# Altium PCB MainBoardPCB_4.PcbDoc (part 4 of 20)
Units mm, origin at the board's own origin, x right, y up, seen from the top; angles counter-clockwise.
Board outline 333.63 x 349.38 mm, 16 copper layers (L1, L2 (GND), L3 (Sign), L4 (GND), L5 (Sign), L6 (PWR/GND), L7(PWR/GND), L8 (Plane_GND), L9 (PWR/GND), L10 (PWR/GND), L11 (PWR/GND), L12 (Sign), L13 (GND), L14 (Sign), L15 (GND), L16), stack 2.502 mm thick; 2205 components, 1648 nets, 8314 pads, 3172 vias.
Unrouted connection lines stored in the file: 5141.
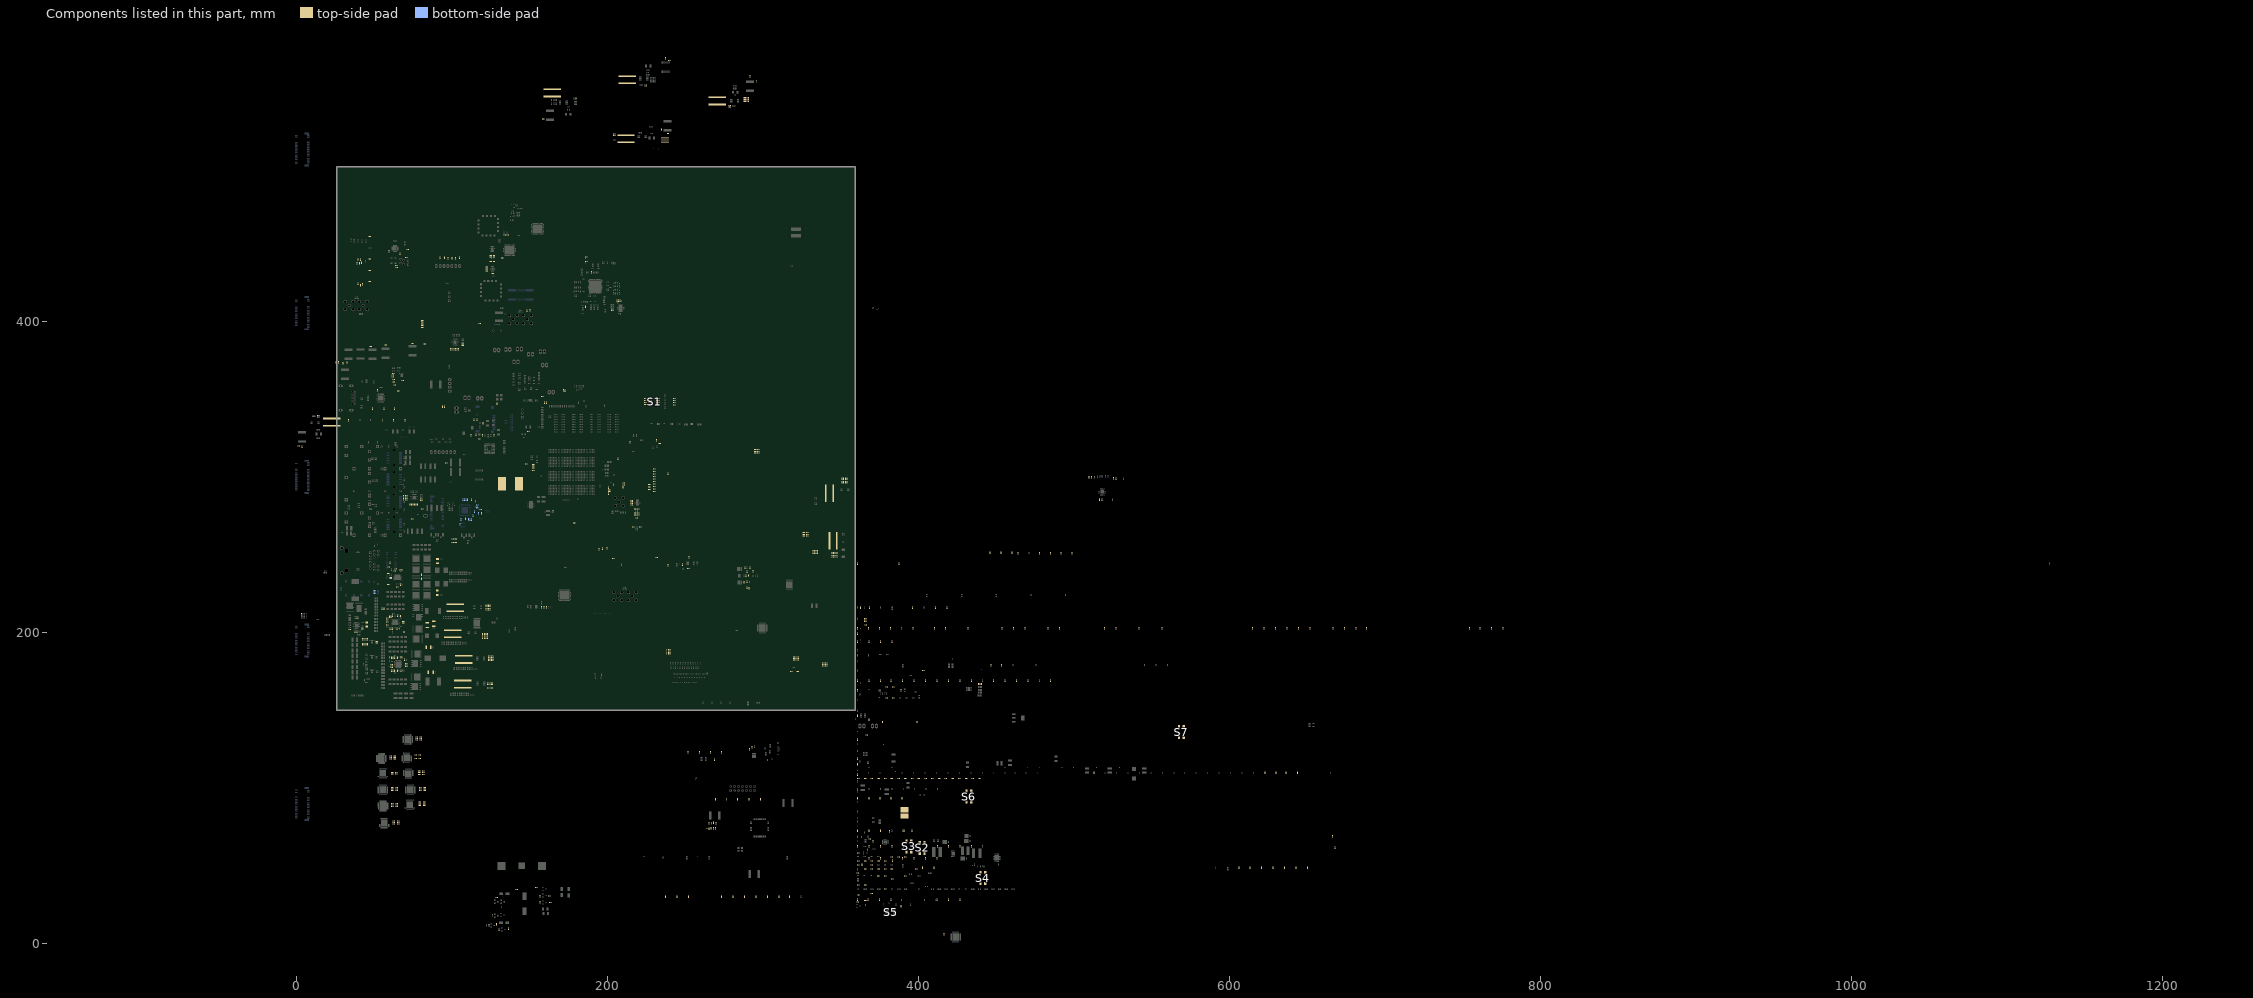
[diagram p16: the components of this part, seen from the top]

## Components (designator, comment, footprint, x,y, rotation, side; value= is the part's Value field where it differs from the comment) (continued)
R199 "0mR" "RES 0402/1005 RF" 3.202,211.734 r90 top
R200 "1.02kR" "RES 0402/1005 RF" 14.092,339.522 r0 top
R201 "0mR" "RES 0402/1005 RF" 288.214,541.35 r180 top
R202 "0mR" "RES 0402/1005 RF" 288.214,542.239 r180 top
R203 "0mR" "RES 0402/1005 RF" 288.214,543.128 r180 top
R204 "0mR" "RES 0402/1005 RF" 288.214,544.017 r180 top
R205 "0mR" "RES 0402/1005 RF" 290.373,541.35 r0 top
R206 "0mR" "RES 0402/1005 RF" 290.373,542.239 r0 top
R207 "0mR" "RES 0402/1005 RF" 290.373,543.128 r0 top
R208 "0mR" "RES 0402/1005 RF" 290.373,544.017 r0 top
R209 "1.02kR" "RES 0402/1005 RF" 278.586,537.724 r180 top
R210 "0mR" "RES 0402/1005 RF" 235.255,515.493 r270 top
R211 "0mR" "RES 0402/1005 RF" 236.525,515.493 r270 top
R212 "12.5k" "RES 0402/1005 RF" 179.728,543.303 r90 top
R213 "0mR" "RES 0402/1005 RF" 237.795,515.493 r270 top
R214 "10kR" "RES 0402/1005 RF" 224.745,551.227 r0 top
R215 "0mR" "RES 0402/1005 RF" 239.065,515.493 r270 top
R216 "31.2kR" "RES 0402/1005 RF" 14.092,338.379 r0 top
R217 "0mR" "RES 0402/1005 RF" 235.255,517.71 r90 top
R218 "10kR" "RES 0402/1005 RF" 278.793,538.867 r180 top
R219 "0mR" "RES 0402/1005 RF" 236.525,517.71 r90 top
R220 "4.99kR" "RES 0402/1005 RF" 205.029,520.065 r90 top
R221 "0mR" "RES 0402/1005 RF" 237.795,517.71 r90 top
R222 "0mR" "RES 0402/1005 RF" 239.065,517.71 r90 top
R223_I2C_Bridge "1kR" "RES 0402/1005 RF" 106.896,385.48 r0 top (schematic designator R223)
R223_I2C_Bridge_2 "1kR" "RES 0402/1005 RF" 509.782,299.86 r90 top (schematic designator R223)
R223_I2C_Bridge_3 "1kR" "RES 0402/1005 RF" 80.422,285.86 r0 top (schematic designator R223)
R224_I2C_Bridge "1kR" "RES 0402/1005 RF" 106.896,384.424 r0 top (schematic designator R224)
R224_I2C_Bridge_2 "1kR" "RES 0402/1005 RF" 525.403,299.047 r90 top (schematic designator R224)
R224_I2C_Bridge_3 "1kR" "RES 0402/1005 RF" 80.422,284.886 r0 top (schematic designator R224)
R225_I2C_Bridge "1kR" "RES 0402/1005 RF" 104.356,382.099 r270 top (schematic designator R225)
R225_I2C_Bridge_2 "1kR" "RES 0402/1005 RF" 516.572,285.382 r90 top (schematic designator R225)
R225_I2C_Bridge_3 "1kR" "RES 0402/1005 RF" 77.941,282.219 r270 top (schematic designator R225)
R226_I2C_Bridge "1kR" "RES 0402/1005 RF" 103.32,382.099 r270 top (schematic designator R226)
R226_I2C_Bridge_2 "1kR" "RES 0402/1005 RF" 511.382,299.682 r90 top (schematic designator R226)
R226_I2C_Bridge_3 "1kR" "RES 0402/1005 RF" 76.975,282.219 r270 top (schematic designator R226)
R227_I2C_Bridge "1kR" "RES 0402/1005 RF" 102.32,382.099 r270 top (schematic designator R227)
R227_I2C_Bridge_2 "1kR" "RES 0402/1005 RF" 527.003,298.869 r90 top (schematic designator R227)
R227_I2C_Bridge_3 "1kR" "RES 0402/1005 RF" 76.01,282.219 r270 top (schematic designator R227)
R228 "1.02kR" "RES 0402/1005 RF" 204.013,520.007 r90 top
R229 "0mR" "RES 0402/1005 RF" 352.006,296.639 r270 top
R230 "0mR" "RES 0402/1005 RF" 350.99,296.639 r270 top
R231_SPI_bridge1 "1kR" "RES 0402/1005 RF" 239.088,301.999 r90 top (schematic designator R231)
R231_SPI_bridge2 "1kR" "RES 0402/1005 RF" 150.127,407.23 r90 top (schematic designator R231)
R231_SPI_bridge3 "1kR" "RES 0402/1005 RF" 74.707,385.724 r180 top (schematic designator R231)
R232_SPI_bridge1 "1kR" "RES 0402/1005 RF" 158.92,530.015 r0 top (schematic designator R232)
R232_SPI_bridge2 "1kR" "RES 0402/1005 RF" 148.476,406.907 r90 top (schematic designator R232)
R232_SPI_bridge3 "1kR" "RES 0402/1005 RF" 62.573,362.737 r0 top (schematic designator R232)
R233_SPI_bridge1 "1kR" "RES 0402/1005 RF" 237.287,569.096 r270 top (schematic designator R233)
R233_SPI_bridge2 "1kR" "RES 0402/1005 RF" 199.632,254.055 r90 top (schematic designator R233)
R233_SPI_bridge3 "1kR" "RES 0402/1005 RF" 96.482,308.945 r180 top (schematic designator R233)
R234_SPI_bridge1 "1kR" "RES 0402/1005 RF" 239.896,567.699 r180 top (schematic designator R234)
R234_SPI_bridge2 "1kR" "RES 0402/1005 RF" 194.75,253.478 r90 top (schematic designator R234)
R234_SPI_bridge3 "1kR" "RES 0402/1005 RF" 62.308,366.547 r0 top (schematic designator R234)
R235_SPI_bridge1 "1kR" "RES 0402/1005 RF" 1.566,319.831 r0 top (schematic designator R235)
R235_SPI_bridge2 "1kR" "RES 0402/1005 RF" 197.036,253.801 r90 top (schematic designator R235)
R235_SPI_bridge3 "1kR" "RES 0402/1005 RF" 62.758,361.066 r0 top (schematic designator R235)
R236_SPI_bridge1 "1kR" "RES 0402/1005 RF" 3.746,319.329 r90 top (schematic designator R236)
R236_SPI_bridge2 "1kR" "RES 0402/1005 RF" 132.575,440.746 r180 top (schematic designator R236)
R236_SPI_bridge3 "1kR" "RES 0402/1005 RF" 47.968,383.819 r180 top (schematic designator R236)
R237_SPI_bridge1 "1kR" "RES 0402/1005 RF" 296.088,554.431 r90 top (schematic designator R237)
R237_SPI_bridge2 "1kR" "RES 0402/1005 RF" 32.474,373.532 r90 top (schematic designator R237)
R237_SPI_bridge3 "1kR" "RES 0402/1005 RF" 61.973,365.404 r0 top (schematic designator R237)
R238_SPI_bridge1 "1kR" "RES 0402/1005 RF" 291.77,557.606 r270 top (schematic designator R238)
R238_SPI_bridge2 "1kR" "RES 0402/1005 RF" 29.934,372.897 r90 top (schematic designator R238)
R238_SPI_bridge3 "1kR" "RES 0402/1005 RF" 57.366,384.708 r180 top (schematic designator R238)
R239_SPI_bridge1 "1kR" "RES 0402/1005 RF" 234.874,523.367 r270 top (schematic designator R239)
R239_SPI_bridge2 "1kR" "RES 0402/1005 RF" 27.013,373.659 r90 top (schematic designator R239)
R239_SPI_bridge3 "1kR" "RES 0402/1005 RF" 61.973,364.261 r0 top (schematic designator R239)
R240_SPI_bridge1 "1kR" "RES 0402/1005 RF" 239.009,520.7 r0 top (schematic designator R240)
R240_SPI_bridge2 "1kR" "RES 0402/1005 RF" 25.489,373.532 r90 top (schematic designator R240)
R240_SPI_bridge3 "1kR" "RES 0402/1005 RF" 82.443,385.47 r180 top (schematic designator R240)
R241 "0mR" "RES 0402/1005 RF" 411.95,54.712 r90 top
R242 "0mR" "RES 0402/1005 RF" 404.584,54.712 r90 top
R243 "0mR" "RES 0402/1005 RF" 397.205,54.712 r90 top
R244 "0mR" "RES 0402/1005 RF" 389.839,54.712 r90 top
R245 "100R" "RES 0402/1005 RF" 218.91,273.456 r180 top
R246 "120R" "RES 0402/1005 RF" 219.895,279.425 r180 top
R247 "127R" "RES 0402/1005 RF" 219.895,275.615 r180 top
R248 "127R" "RES 0402/1005 RF" 217.794,275.615 r0 top
R249 "120R" "RES 0402/1005 RF" 217.794,279.425 r180 top
R250 "82.5R" "RES 0402/1005 RF" 219.895,276.631 r180 top
R251 "82.5R" "RES 0402/1005 RF" 217.794,276.631 r0 top
R252 "1kR" "RES 0402/1005 RF" 215.227,284.447 r90 top
R253 "1kR" "RES 0402/1005 RF" 215.227,282.443 r270 top
R254 "1kR" "RES 0402/1005 RF" 216.243,284.447 r270 top
R255 "1kR" "RES 0402/1005 RF" 216.243,282.443 r90 top
R256 "120R" "RES 0402/1005 RF" 127.114,438.587 r180 top
R257 "49.9R" "RES 0402/1005 RF" 126.421,430.713 r180 top
R258 "120R" "RES 0402/1005 RF" 125.177,438.587 r180 top
R259 "82.5R" "RES 0402/1005 RF" 125.177,442.397 r0 top
R260 "82.5R" "RES 0402/1005 RF" 127.114,442.397 r180 top
R261 "127R" "RES 0402/1005 RF" 125.177,441.381 r0 top
R262 "127R" "RES 0402/1005 RF" 127.114,441.381 r180 top
R263 "60.4kR" "RES 0402/1005 RF" 122.6,432.364 r0 top
R264 "0mR" "RES 0402/1005 RF" 122.6,434.874 r0 top
R265 "0mR" "RES 0402/1005 RF" 122.6,433.649 r0 top
R266 "84.5kR" "RES 0402/1005 RF" 60.181,244.78 r90 top
R267 "4.7kR" "RES 0402/1005 RF" 370.04,32.182 r0 top
R268 "2R" "RES 0402/1005 RF" 59.242,237.714 r0 top
R269 "1.02kR" "RES 0402/1005 RF" 361.511,31.064 r0 top
R270 "160R" "RES 0402/1005 RF" 238.976,243.23 r270 top
R271 "5kR" "RES 0402/1005 RF" 61.041,240.32 r90 top
R272 "2R" "RES 0402/1005 RF" 60.606,235.139 r180 top
R273 "12kR" "RES 0402/1005 RF" 63.389,239.52 r180 top
R274 "10kR" "RES 0402/1005 RF" 398.704,47.739 r0 top
R275 "47kR" "RES 0402/1005 RF" 80.488,236.914 r90 top
R276 "4.7kR" "RES 0402/1005 RF" 214.452,322.344 r270 top
R277 "12kR" "RES 0402/1005 RF" 64.94,229.317 r0 top
R278 "12kR" "RES 0402/1005 RF" 63.889,240.855 r0 top
R279 "0mR" "RES 0402/1005 RF" 383.045,47.739 r0 top
R280 "47kR" "RES 0402/1005 RF" 80.488,234.339 r270 top
R281 "0mR" "RES 0402/1005 RF" 383.481,53.104 r90 top
R282 "0mR" "RES 0402/1005 RF" 378.714,47.739 r0 top
R283 "0mR" "RES 0402/1005 RF" 374.383,47.739 r0 top
R284 "18.2k (1MHz)" "RES 0402/1005 RF" 378.663,34.963 r0 top
R285 "2R" "RES 0402/1005 RF" 59.753,184.12 r270 top
R286 "0mR" "RES 0402/1005 RF" 370.053,47.739 r0 top
R287 "49.9kR" "RES 0402/1005 RF" 61.241,183.809 r90 top
R288 "Resistor_1210" RES_1210 85.014,190.309 r180 top value=3.6R
R289 "2R" "RES 0402/1005 RF" 61.331,179.317 r180 top
R290 "10kR" "RES 0402/1005 RF" 62.191,183.809 r270 top
R291 "150R" "RES 0402/1005 RF" 365.722,47.739 r0 top
R292 "Resistance" "RES 0402/1005 RF" 70.661,179.917 r180 top
R293 "0mR" "RES 0402/1005 RF" 61.331,178.317 r0 top
R294 "0mR" "RES 0402/1005 RF" 61.331,177.317 r0 top
R295 "12kR" "RES 0402/1005 RF" 67.169,183.85 r270 top
R296 "12kR" "RES 0402/1005 RF" 67.204,175.367 r90 top
R297 "10kR" "RES 0402/1005 RF" 62.14,175.401 r270 top
R298 "Resistor_1210" RES_1210 86.39,174.414 r180 top value=3.6R
R299 "47kR" "RES 0402/1005 RF" 70.661,179.067 r180 top
R300 "10kR" "RES 0402/1005 RF" 61.068,175.401 r90 top
R301 "150R" "RES 0402/1005 RF" 391.655,43.434 r0 top
R302 "1.4kR" "RES 0201/0603" 66.453,202.488 r90 top
R303 "2R" "RES 0402/1005 RF" 55.203,215.087 r270 top
R304 "0mR" "RES 0402/1005 RF" 117.92,398.695 r0 top
R305 "100R" "RES 0402/1005 RF" 383.154,41.402 r0 top
R306 "Resistor_1210" RES_1210 88.316,205.562 r90 top value=3.6R
R307 "2R" "RES 0402/1005 RF" 58.395,206.596 r0 top
R308 "100R" "RES 0402/1005 RF" 378.689,43.434 r0 top
R309 "100R" "RES 0402/1005 RF" 374.358,43.434 r0 top
R310 "0mR" "RES 0402/1005 RF" 58.395,208.526 r180 top
R311 "100R" "RES 0402/1005 RF" 368.676,67.005 r0 top
R312 "0mR" "RES 0402/1005 RF" 58.376,204.716 r0 top
R313 "12kR" "RES 0402/1005 RF" 64.953,210.754 r270 top
R314 "12kR" "RES 0402/1005 RF" 64.623,202.273 r90 top
R315 "196kR" "RES 0402/1005 RF" 61.041,202.273 r270 top
R316 "Resistor_1210" RES_1210 84.163,204.643 r270 top value=3.6R
R317 "47kR" "RES 0402/1005 RF" 68.656,206.039 r180 top
R318 "27kR" "RES 0402/1005 RF" 60.114,202.273 r90 top
R319 "10kR" "RES 0402/1005 RF" 117.299,276.692 r90 bottom
R320 "10kR" "RES 0402/1005 RF" 115.069,284.177 r90 bottom
R321 "100R" "RES 0402/1005 RF" 119.191,276.704 r90 bottom
R322 "5.76kR" "RES 0402/1005 RF" 113.468,274.906 r90 bottom
R323 "5.76kR" "RES 0402/1005 RF" 114.688,277.499 r90 bottom
R324 "100kR" "RES 0805/2012 RF" 50.292,225.882 r90 bottom
R325 "2.49kR" "RES 0402/1005 RF" 118.694,279.122 r0 bottom
R326 "2.49kR" "RES 0402/1005 RF" 116.313,279.884 r0 bottom
R327 "2.49kR" "RES 0402/1005 RF" 116.072,280.722 r0 bottom
R328 "2.49kR" "RES 0402/1005 RF" 116.402,281.809 r0 bottom
R329 "100R" "RES 0402/1005 RF" 107.08,285.243 r90 bottom
R330 "100R" "RES 0402/1005 RF" 108.16,285.205 r90 bottom
R331 "100R" "RES 0402/1005 RF" 109.176,285.251 r90 bottom
R332 "100R" "RES 0402/1005 RF" 112.694,285.243 r270 bottom
R333 "2.2kR" "RES 0402/1005 RF" 108.79,272.944 r90 bottom
R334 "11kR" "RES 0402/1005" 105.81,272.708 r270 bottom
R335 "1MR" "RES 0402/1005 RF" 105.112,269.597 r90 bottom
R336 "2.2kR" "RES 0402/1005 RF" 112.702,272.331 r90 bottom
R337 "2.2kR" "RES 0402/1005 RF" 110.649,272.581 r90 bottom
R338 "2.2kR" "RES 0402/1005 RF" 111.614,272.449 r90 bottom
R339 "105kR" "RES 0402/1005 RF" 120.155,334.607 r90 top
R340 "10kR" "RES 0402/1005 RF" 116.087,336.73 r90 top
R341 "15kR" "RES 0402/1005 RF" 114.38,336.692 r90 top
R342 "105kR" "RES 0402/1005 RF" 115.595,327.144 r90 top
R343 "10kR" "RES 0402/1005 RF" 127.203,326.801 r90 top
R344 "15kR" "RES 0402/1005 RF" 119.837,326.801 r90 top
R345 "0R" "RES 0402/1005 RF" 112.471,326.801 r90 top
R346 "4.7kR" "RES 0402/1005 RF" 70.724,441.147 r0 top
R347 "4.7kR" "RES 0402/1005 RF" 147.859,307.142 r0 top
R348 "4.7kR" "RES 0402/1005 RF" 147.917,308.254 r0 top
R349 "4.7kR" "RES 0402/1005 RF" 243.109,346.354 r0 top
R350 "4.7kR" "RES 0402/1005 RF" 243.109,347.667 r0 top
R351 "4.7kR" "RES 0402/1005 RF" 243.109,348.979 r0 top
R352 "4.7kR" "RES 0402/1005 RF" 243.109,350.291 r0 top
R353 "4.7kR" "RES 0402/1005 RF" 39.771,424.265 r90 top
R354 "4.7kR" "RES 0402/1005 RF" 64.224,435.813 r0 top
R355 "4.7kR" "RES 0402/1005 RF" 64.605,434.543 r0 top
R356 "4.7kR" "RES 0402/1005 RF" 42.498,423.815 r270 top
R357 "4.7kR" "RES 0402/1005 RF" 41.198,423.365 r90 top
R358 "499R" "RES 0402/1005 RF" 224.515,346.472 r180 top
R359 "499R" "RES 0402/1005 RF" 224.315,347.751 r180 top
R360 "499R" "RES 0402/1005 RF" 224.315,349.021 r180 top
R361 "499R" "RES 0402/1005 RF" 224.315,350.291 r180 top
R362 "30R" "RES 0402/1005 RF" 39.009,437.413 r90 top
R363 "4.7kR" "RES 0402/1005 RF" 39.771,439.768 r90 top
R364 "4.7kR" "RES 0402/1005 RF" 40.548,437.482 r90 top
R365 "4.7kR" "RES 0402/1005 RF" 41.93,437.54 r90 top
R366 "10kR" "RES 0402/1005 RF" 41.295,439.699 r90 top
R367 "4.7kR" "RES 0402/1005 RF" 71.74,446.303 r0 top
R368 "261R" "RES 0402/1005 RF" 47.333,454.431 r180 top
R369 "10kR" "RES 0402/1005 RF" 66.787,443.56 r90 top
R370 "10kR" "RES 0402/1005 RF" 47.333,425.475 r180 top
R371 "10kR" "RES 0402/1005 RF" 47.333,432.841 r180 top
R372 "8.06kR" "RES 0402/1005 RF" 47.333,440.207 r180 top
R373 "10kR" "RES 0402/1005 RF" 59.548,445.084 r90 top
R374 "4.7MR" "RES 0402/1005 RF" 149.073,329.222 r0 top
R375 "40.2R" "RES 0402/1005 RF" 129.107,347.154 r270 top
R376 "0R" "RES 0402/1005 RF" 69.977,336.448 r90 top
R377 "0R" "RES 0402/1005 RF" 62.611,336.448 r90 top
R378 "0R" "RES 0402/1005 RF" 55.245,336.448 r90 top
R379 "8.06kR" "RES 0402/1005 RF" 33.655,336.448 r90 top
R380 "4.22kR" "RES 0402/1005 RF" 453.555,178.905 r90 top
R381 "4.7kR" "RES 0402/1005 RF" 418.3,215.862 r90 top
R382 "4.7kR" "RES 0402/1005 RF" 410.921,215.862 r90 top
R383 "10kR" "RES 0402/1005 RF" 396.189,215.862 r90 top
R384 "71.5R" "RES 0402/1005 RF" 365.76,208.915 r0 top
R385 "71.5R" "RES 0402/1005 RF" 365.76,207.899 r0 top
R386 "8.87kR" "RES 0402/1005 RF" 365.76,206.883 r0 top
R387 "5.1kR" "RES 0402/1005 RF" 366.23,204.826 r0 top
R388 "0mR" "RES 0402/1005 RF" 289.784,228.694 r90 top
R389 "0mR" "RES 0402/1005 RF" 291.054,228.509 r90 top
R390 "0mR" "RES 0402/1005 RF" 289.911,238.904 r90 top
R391 "75kR" "RES 0402/1005 RF" 291.689,241.571 r90 top
R392 "100kR" "RES 0402/1005 RF" 288.514,241.571 r90 top
R393 "15kR" "RES 0402/1005 RF" 293.721,239.354 r90 top
R394 "51.1kR" "RES 0402/1005 RF" 289.911,232.604 r90 top
R395 "10kR" "RES 0402/1005 RF" 439.318,105.893 r0 top
R396 "15kR" "RES 0402/1005 RF" 287.879,232.104 r90 top
R397 "21.5kR" "RES 0402/1005 RF" 290.673,236.562 r90 top
R398 "10kR" "RES 0402/1005 RF" 434.988,105.893 r0 top
R399 "15kR" "RES 0402/1005 RF" 289.276,236.435 r90 top
R400 "0mR" "RES 0402/1005 RF" 375.615,54.712 r90 top
R401 "10k" "RES 0402/1005 RF" 265.244,73.834 r90 top
R402 "0R" "RES 0402/1005 RF" 266.818,77.114 r90 top
R403 "0R" "RES 0402/1005 RF" 268.292,74.038 r90 top
R404 "0R" "RES 0402/1005 RF" 269.866,77.318 r90 top
R405 "0R" "RES 0402/1005 RF" 269.588,73.961 r90 top
R406 "0R" "RES 0402/1005 RF" 265.32,77.241 r90 top
R407 "0R" "RES 0402/1005 RF" 266.794,74.165 r90 top
R408 "0R" "RES 0402/1005 RF" 268.368,77.445 r90 top
R409 "0R" "RES 0402/1005 RF" 498.805,250.965 r90 top
R410 "10k" "RES 0402/1005 RF" 491.693,250.965 r90 top
R411 "0R" "RES 0402/1005 RF" 485.089,250.965 r90 top
R412 "0R" "RES 0402/1005 RF" 477.977,250.965 r90 top
R413 "0R" "RES 0402/1005 RF" 464.007,250.965 r90 top
R414 "0R" "RES 0402/1005 RF" 460.273,251.338 r90 top
R415 "0R" "RES 0402/1005 RF" 453.161,251.338 r90 top
R416 "0R" "RES 0402/1005 RF" 446.037,251.338 r90 top
R417 "10k" "RES 0402/1005 RF" 273.337,122.949 r90 top
R418 "0R" "RES 0402/1005 RF" 268.808,118.161 r90 top
R419 "2kR" "RES 0402/1005 RF" 266.225,122.949 r90 top
R420 "10k" "RES 0402/1005 RF" 251.989,122.949 r90 top
R421 "0R" "RES 0402/1005 RF" 259.355,122.949 r90 top
R422 "10k" "RES 0402/1005 RF" 303.035,29.858 r90 top
R423 "12kR" "RES 0402/1005 RF" 410.159,48.476 r90 top
R424 "1kR" "RES 0402/1005 RF" 402.793,48.476 r90 top
R425 "4.7kR" "RES 0402/1005 RF" 74.647,272.784 r0 top
R426 "4.7kR" "RES 0402/1005 RF" 74.765,271.767 r0 top
R427 "1kR" "RES 0402/1005 RF" 365.722,37.401 r0 top
R428 "1kR" "RES 0402/1005 RF" 368.249,54.712 r90 top
R429 "0mR" "RES 0402/1005 RF" 80.988,279.244 r0 top
R430_5V_to_3V3_for_FTDI "105kR" "RES 0402/1005 RF" 291.541,124.892 r90 top (schematic designator R430)
R430_U_5V_to_3V31 "105kR" "RES 0402/1005 RF" 160.801,216.124 r270 top (schematic designator R430)
R430_U_5V_to_3V32 "105kR" "RES 0402/1005 RF" 248.361,243.489 r270 top (schematic designator R430)
R430_U_5V_to_3V33 "105kR" "RES 0402/1005 RF" 65.425,355.117 r0 top (schematic designator R430)
R431_5V_to_3V3_for_FTDI "100kR" "RES 0402/1005 RF" 294.792,126.363 r90 top (schematic designator R431)
R431_U_5V_to_3V31 "100kR" "RES 0402/1005 RF" 157.728,216.123 r90 top (schematic designator R431)
R431_U_5V_to_3V32 "100kR" "RES 0402/1005 RF" 252.578,248.374 r90 top (schematic designator R431)
R431_U_5V_to_3V33 "100kR" "RES 0402/1005 RF" 68.468,361.848 r0 top (schematic designator R431)
R432_5V_to_3V3_for_FTDI "15kR" "RES 0402/1005 RF" 293.027,126.211 r90 top (schematic designator R432)
R432_U_5V_to_3V31 "15kR" "RES 0402/1005 RF" 159.201,216.148 r90 top (schematic designator R432)
R432_U_5V_to_3V32 "15kR" "RES 0402/1005 RF" 252.019,241.198 r180 top (schematic designator R432)
R432_U_5V_to_3V33 "15kR" "RES 0402/1005 RF" 63.208,358.927 r0 top (schematic designator R432)
R433 "56kR" "RES 0402/1005 RF" 383.921,157.861 r0 top
R434 "10kR" "RES 0402/1005 RF" 379.603,157.861 r0 top
R435 "10kR" "RES 0402/1005 RF" 368.719,215.913 r90 top
R436 "3.57kR" "RES 0402/1005 RF" 202.527,407.496 r90 top
R437 "1.15kR" "RES 0402/1005 RF" 403.213,175.514 r0 top
R438 "3.57kR" "RES 0402/1005 RF" 207.049,413.148 r90 top
R439 "1.15kR" "RES 0402/1005 RF" 206.083,413.148 r270 top
R440 "20kR" "RES 0402/1005 RF" 203.604,407.496 r90 top
R441 "20kR" "RES 0402/1005 RF" 207.996,413.148 r90 top
R442 "100kR" "RES 0402/1005 RF" 360.934,199.009 r90 top
R443 "698kR" "RES 0805/2012 RF" 439.547,166.751 r0 top
R444 "49.9kR" "RES 0402/1005 RF" 383.921,164.973 r0 top
R445 "49.9kR" "RES 0402/1005 RF" 379.603,164.973 r0 top
R446 "120R" "RES 0402/1005 RF" 388.785,162.738 r90 top
R447 "120R" "RES 0402/1005 RF" 360.883,162.738 r90 top
R448_U_Pomiar_pradu_napiecia_1 "FCSL110R005FER" FCSL110R005FERCT-ND 342.862,289.458 r0 top (schematic designator R448)
R448_U_Pomiar_pradu_napiecia_2 "FCSL110R005FER" FCSL110R005FERCT-ND 345.148,258.851 r180 top (schematic designator R448)
R448_U_Pomiar_pradu_napiecia_3 "FCSL110R005FER" FCSL110R005FERCT-ND 107.759,182.601 r90 top (schematic designator R448)
R448_U_Pomiar_pradu_napiecia_4 "FCSL110R005FER" FCSL110R005FERCT-ND 106.904,166.738 r90 top (schematic designator R448)
R448_U_Pomiar_pradu_napiecia_5 "FCSL110R005FER" FCSL110R005FERCT-ND 102.092,215.887 r90 top (schematic designator R448)
R448_U_Pomiar_pradu_napiecia_6 "FCSL110R005FER" FCSL110R005FERCT-ND 100.635,199.06 r90 top (schematic designator R448)
R448_U_Pomiar_pradu_napiecia_7 "FCSL110R005FER" FCSL110R005FERCT-ND 164.668,546.875 r90 top (schematic designator R448)
R448_U_Pomiar_pradu_napiecia_8 "FCSL110R005FER" FCSL110R005FERCT-ND 212.776,555.38 r90 top (schematic designator R448)
R448_U_Pomiar_pradu_napiecia_9 "FCSL110R005FER" FCSL110R005FERCT-ND 22.669,335.204 r270 top (schematic designator R448)
R448_U_Pomiar_pradu_napiecia_10 "FCSL110R005FER" FCSL110R005FERCT-ND 270.688,541.731 r270 top (schematic designator R448)
R448_U_Pomiar_pradu_napiecia_11 "FCSL110R005FER" FCSL110R005FERCT-ND 212.014,517.398 r90 top (schematic designator R448)
R449 "0mR" "RES 0402/1005 RF" 81.09,400.473 r0 top
R450 "0mR" "RES 0402/1005 RF" 81.09,399.457 r0 top
R451 "0mR" "RES 0402/1005 RF" 81.09,395.901 r0 top
R452 "0mR" "RES 0402/1005 RF" 80.963,401.997 r0 top
R453 "0mR" "RES 0402/1005 RF" 81.09,397.229 r0 top
R454 "0mR" "RES 0402/1005 RF" 81.09,398.314 r0 top
R455 "0mR" "RES 0402/1005 RF" 240.373,186.426 r270 top
R455_1 "0mR" "RES 0402/1005 RF" 61.698,90.027 r180 top (schematic designator R455)
R456 "0mR" "RES 0402/1005 RF" 240.373,188.458 r90 top
R456_1 "0mR" "RES 0402/1005 RF" 64.629,90.027 r0 top (schematic designator R456)
R457 "0mR" "RES 0402/1005 RF" 353.022,296.639 r270 top
R458 "0mR" "RES 0402/1005 RF" 239.357,186.426 r270 top
R458_1 "0mR" "RES 0402/1005 RF" 61.697,88.983 r180 top (schematic designator R458)
R459 "0mR" "RES 0402/1005 RF" 354.038,296.639 r270 top
R460 "0mR" "RES 0402/1005 RF" 239.357,188.458 r90 top
R460_1 "0mR" "RES 0402/1005 RF" 64.629,88.983 r0 top (schematic designator R460)
R461 "0mR" "RES 0402/1005 RF" 352.006,298.671 r90 top
R462 "0mR" "RES 0402/1005 RF" 238.214,186.426 r270 top
R462_1 "0mR" "RES 0402/1005 RF" 61.698,87.962 r180 top (schematic designator R462)
R463 "0mR" "RES 0402/1005 RF" 350.99,298.671 r90 top
R464 "0mR" "RES 0402/1005 RF" 238.214,188.458 r90 top
R464_1 "0mR" "RES 0402/1005 RF" 64.629,87.962 r0 top (schematic designator R464)
R465 "0mR" "RES 0402/1005 RF" 353.022,298.671 r90 top
R466 "0mR" "RES 0402/1005 RF" 354.038,298.671 r90 top
R467 "0mR" "RES 0402/1005 RF" 345.529,249.003 r270 top
R468 "0mR" "RES 0402/1005 RF" 344.513,249.003 r270 top
R469 "0mR" "RES 0402/1005 RF" 69.041,287.622 r90 top
R470 "0mR" "RES 0402/1005 RF" 69.041,285.648 r270 top
R471 "0mR" "RES 0402/1005 RF" 70.057,287.622 r90 top
R472 "0mR" "RES 0402/1005 RF" 70.057,285.648 r270 top
R473 "0mR" "RES 0402/1005 RF" 71.073,287.622 r90 top
R474 "0mR" "RES 0402/1005 RF" 71.073,285.648 r270 top
R475 "0mR" "RES 0402/1005 RF" 102.629,259.923 r0 top
R475_1 "0mR" "RES 0402/1005 RF" 60.714,118.511 r180 top (schematic designator R475)
R476 "0mR" "RES 0402/1005 RF" 100.655,259.923 r180 top
R476_1 "0mR" "RES 0402/1005 RF" 63.426,118.519 r0 top (schematic designator R476)
R477 "0mR" "RES 0402/1005 RF" 102.629,258.907 r0 top
R477_1 "0mR" "RES 0402/1005 RF" 60.718,119.548 r180 top (schematic designator R477)
R478 "0mR" "RES 0402/1005 RF" 100.655,258.907 r180 top
R478_1 "0mR" "RES 0402/1005 RF" 63.43,119.556 r0 top (schematic designator R478)
R479 "0mR" "RES 0402/1005 RF" 102.629,257.845 r0 top
R479_1 "0mR" "RES 0402/1005 RF" 60.718,120.592 r180 top (schematic designator R479)
R480 "0mR" "RES 0402/1005 RF" 100.655,257.845 r180 top
R480_1 "0mR" "RES 0402/1005 RF" 63.43,120.6 r0 top (schematic designator R480)
R481 "0R" "RES 0402/1005 RF" 178.867,270.281 r0 top
R482 "150R" "RES 0402/1005 RF" 201.072,291.539 r180 top
R483 "150R" "RES 0402/1005 RF" 201.072,290.539 r180 top
R484 "71.5R" "RES 0402/1005 RF" 200.622,292.989 r270 top
R485 "71.5R" "RES 0402/1005 RF" 200.622,289.089 r90 top
R486 "8.87kR" "RES 0402/1005 RF" 203.797,294.82 r90 top
R487 "5.1kR" "RES 0402/1005 RF" 210.555,294.895 r180 top
R488 "1kR" "RES 0402/1005 RF" 210.555,295.911 r180 top
R489 "100R" "RES 0402/1005 RF" 210.105,293.423 r90 top
R490 "10kR" "RES 0402/1005 RF" 52.083,355.6 r90 top
R491 "1MR" "RES 0402/1005 RF" 446.697,178.905 r90 top
R492 "0mR" "RES 0402/1005 RF" 320.345,184.208 r180 top
R492_1 "0mR" "RES 0402/1005 RF" 79.263,88.634 r180 top (schematic designator R492)
R493 "0mR" "RES 0402/1005 RF" 322.377,184.208 r0 top
R493_1 "0mR" "RES 0402/1005 RF" 82.159,88.64 r0 top (schematic designator R493)
R494 "0mR" "RES 0402/1005 RF" 320.345,183.134 r180 top
R494_1 "0mR" "RES 0402/1005 RF" 79.263,89.74 r180 top (schematic designator R494)
R495 "0mR" "RES 0402/1005 RF" 322.377,183.134 r0 top
R495_1 "0mR" "RES 0402/1005 RF" 82.159,89.733 r0 top (schematic designator R495)
R496 "0mR" "RES 0402/1005 RF" 320.345,182.118 r180 top
R496_1 "0mR" "RES 0402/1005 RF" 79.263,90.833 r180 top (schematic designator R496)
R497 "0mR" "RES 0402/1005 RF" 322.377,182.118 r0 top
R497_1 "0mR" "RES 0402/1005 RF" 82.158,90.833 r0 top (schematic designator R497)
R498 "0R" "RES 0402/1005 RF" 322.589,174.921 r0 top
R499 "1kR" "RES 0402/1005 RF" 318.271,174.921 r0 top
R500 "0mR" "RES 0402/1005 RF" 338.829,180.398 r180 top
R500_1 "0mR" "RES 0402/1005 RF" 61.84,98.264 r180 top (schematic designator R500)
R501 "0mR" "RES 0402/1005 RF" 340.861,180.398 r0 top
R501_1 "0mR" "RES 0402/1005 RF" 64.629,98.266 r0 top (schematic designator R501)
R502 "0mR" "RES 0402/1005 RF" 338.829,178.308 r180 top
R502_1 "0mR" "RES 0402/1005 RF" 61.84,99.316 r180 top (schematic designator R502)
R503 "0mR" "RES 0402/1005 RF" 340.861,178.308 r0 top
R503_1 "0mR" "RES 0402/1005 RF" 64.629,99.319 r0 top (schematic designator R503)
R504 "0mR" "RES 0402/1005 RF" 338.829,179.324 r180 top
R504_1 "0mR" "RES 0402/1005 RF" 61.84,100.364 r180 top (schematic designator R504)
R505 "0mR" "RES 0402/1005 RF" 340.861,179.324 r0 top
R505_1 "0mR" "RES 0402/1005 RF" 64.629,100.366 r0 top (schematic designator R505)
R506 "10kR" "RES 0402/1005 RF" 226.795,306.502 r180 top
R507 "10kR" "RES 0402/1005 RF" 230.206,290.614 r180 top
R508 "0mR" "RES 0402/1005 RF" 295.013,317.456 r180 top
R508_1 "0mR" "RES 0402/1005 RF" 79.704,98.272 r180 top (schematic designator R508)
R509 "0mR" "RES 0402/1005 RF" 297.045,317.456 r0 top
R509_1 "0mR" "RES 0402/1005 RF" 82.697,98.272 r0 top (schematic designator R509)
R510 "0mR" "RES 0402/1005 RF" 295.013,316.382 r180 top
R510_1 "0mR" "RES 0402/1005 RF" 79.704,99.3 r180 top (schematic designator R510)
R511 "0mR" "RES 0402/1005 RF" 297.045,316.382 r0 top
R511_1 "0mR" "RES 0402/1005 RF" 82.697,99.316 r0 top (schematic designator R511)
R512 "0mR" "RES 0402/1005 RF" 295.013,315.366 r180 top
R512_1 "0mR" "RES 0402/1005 RF" 79.705,100.316 r180 top (schematic designator R512)
R513 "0mR" "RES 0402/1005 RF" 297.045,315.366 r0 top
R513_1 "0mR" "RES 0402/1005 RF" 82.697,100.316 r0 top (schematic designator R513)
R514 "10kR" "RES 0402/1005 RF" 226.795,303.282 r180 top
R515 "10kR" "RES 0402/1005 RF" 226.795,301.671 r180 top
R516 "0mR" "RES 0402/1005 RF" 332.633,252.686 r180 top
R516_1 "0mR" "RES 0402/1005 RF" 76.803,121.107 r180 top (schematic designator R516)
R517 "0mR" "RES 0402/1005 RF" 334.665,252.686 r0 top
R517_1 "0mR" "RES 0402/1005 RF" 79.421,121.107 r0 top (schematic designator R517)
R518 "0mR" "RES 0402/1005 RF" 332.633,251.612 r180 top
R518_1 "0mR" "RES 0402/1005 RF" 76.803,120.002 r180 top (schematic designator R518)
R519 "0mR" "RES 0402/1005 RF" 334.665,251.612 r0 top
R519_1 "0mR" "RES 0402/1005 RF" 79.421,120.002 r0 top (schematic designator R519)
R520 "0mR" "RES 0402/1005 RF" 332.633,250.596 r180 top
R520_1 "0mR" "RES 0402/1005 RF" 76.804,118.89 r180 top (schematic designator R520)
R521 "0mR" "RES 0402/1005 RF" 334.665,250.596 r0 top
R521_1 "0mR" "RES 0402/1005 RF" 79.423,118.89 r0 top (schematic designator R521)
R522 "10kR" "RES 0402/1005 RF" 226.795,292.009 r180 top
R523 "10kR" "RES 0402/1005 RF" 226.795,293.62 r180 top
R524 "0mR" "RES 0402/1005 RF" 326.436,264.116 r180 top
R525 "0mR" "RES 0402/1005 RF" 328.468,264.116 r0 top
R526 "0mR" "RES 0402/1005 RF" 326.436,263.042 r180 top
R527 "0mR" "RES 0402/1005 RF" 328.468,263.042 r0 top
R528 "0mR" "RES 0402/1005 RF" 326.436,262.026 r180 top
R529 "0mR" "RES 0402/1005 RF" 328.468,262.026 r0 top
R530 "10kR" "RES 0402/1005 RF" 226.795,296.84 r180 top
R531 "10kR" "RES 0402/1005 RF" 226.795,295.23 r180 top
R532 "75R" "RES 0402/1005 RF" 133.96,455.478 r180 top
R533 "30R" "RES 0402/1005 RF" 136.05,455.478 r180 top
R534 "100R" "RES 0402/1005 RF" 231.864,248.056 r0 top
R535 "100R" "RES 0402/1005 RF" 203.797,247.548 r0 top
R536 "150R" "RES 0402/1005 RF" 216.76,267.632 r180 top
R537 "150R" "RES 0402/1005 RF" 221.11,267.632 r180 top
R538 "1kR" "RES 0402/1005 RF" 361.391,37.401 r0 top
R539 "160R" "RES 0402/1005 RF" 209.258,243.484 r270 top
R540 "0R" "RES 0402/1005 RF" 189.88,431.485 r270 top
R541 "100R" "RES 0402/1005 RF" 368.249,143.916 r90 top
R542 "100R" "RES 0402/1005 RF" 360.807,146.26 r90 top
R543 "100R" "RES 0402/1005 RF" 186.34,441.365 r180 top
R544 "1kR" "RES 0402/1005 RF" 186.017,409.532 r90 top
R545 "49.9R" "RES 0402/1005 RF" 186.34,438.571 r180 top
R546 "10kR" "RES 0402/1005 RF" 230.206,301.886 r180 top
R547 "10kR" "RES 0402/1005 RF" 226.795,300.061 r180 top
R548 "10kR" "RES 0402/1005 RF" 230.206,300.276 r180 top
R549 "10kR" "RES 0402/1005 RF" 230.206,297.055 r180 top
R550 "10kR" "RES 0402/1005 RF" 230.206,303.497 r180 top
R551 "10kR" "RES 0402/1005 RF" 230.206,295.445 r180 top
R552 "10kR" "RES 0402/1005 RF" 230.206,292.224 r180 top
R553 "10kR" "RES 0402/1005 RF" 230.206,305.107 r180 top
R554 "10kR" "RES 0402/1005 RF" 230.206,298.666 r180 top
R555 "10kR" "RES 0402/1005 RF" 230.206,293.835 r180 top
R556 "10kR" "RES 0402/1005 RF" 226.795,304.892 r180 top
R557 "10kR" "RES 0402/1005 RF" 226.795,298.451 r180 top
R558_I2C_Bridge "1kR" "RES 0402/1005 RF" 101.32,382.099 r270 top (schematic designator R558)
R558_I2C_Bridge_2 "1kR" "RES 0402/1005 RF" 518.173,285.204 r90 top (schematic designator R558)
R558_I2C_Bridge_3 "1kR" "RES 0402/1005 RF" 75.045,282.219 r270 top (schematic designator R558)
R559_I2C_Bridge "1kR" "RES 0402/1005 RF" 100.135,382.099 r270 top (schematic designator R559)
R559_I2C_Bridge_2 "1kR" "RES 0402/1005 RF" 387.541,244.17 r90 top (schematic designator R559)
R559_I2C_Bridge_3 "1kR" "RES 0402/1005 RF" 74.079,282.219 r270 top (schematic designator R559)
R560_I2C_Bridge "1kR" "RES 0402/1005 RF" 99.022,382.099 r270 top (schematic designator R560)
R560_I2C_Bridge_2 "1kR" "RES 0402/1005 RF" 360.883,244.17 r90 top (schematic designator R560)
R560_I2C_Bridge_3 "1kR" "RES 0402/1005 RF" 73.114,282.219 r270 top (schematic designator R560)
R561 "0mR" "RES 0402/1005 RF" 124.498,184.31 r90 top
R562 "0mR" "RES 0402/1005 RF" 123.482,184.31 r90 top
R563 "0mR" "RES 0402/1005 RF" 125.514,184.31 r90 top
R564 "0mR" "RES 0402/1005 RF" 126.53,184.31 r90 top
R565 "0mR" "RES 0402/1005 RF" 124.498,182.278 r270 top
R566 "0mR" "RES 0402/1005 RF" 123.482,182.278 r270 top
R567 "0mR" "RES 0402/1005 RF" 125.514,182.278 r270 top
R568 "0mR" "RES 0402/1005 RF" 126.53,182.278 r270 top
R569 "0mR" "RES 0402/1005 RF" 125.539,165.349 r0 top
R570 "0mR" "RES 0402/1005 RF" 125.539,164.333 r0 top
R571 "0mR" "RES 0402/1005 RF" 125.539,166.365 r0 top
R572 "0mR" "RES 0402/1005 RF" 125.54,167.381 r0 top
R573 "0mR" "RES 0402/1005 RF" 123.507,165.349 r180 top
R574 "0mR" "RES 0402/1005 RF" 123.508,164.333 r180 top
R575 "0mR" "RES 0402/1005 RF" 123.508,166.365 r180 top
R576 "0mR" "RES 0402/1005 RF" 123.508,167.381 r180 top
R577 "0mR" "RES 0402/1005 RF" 122.504,216.987 r90 top
R578 "0mR" "RES 0402/1005 RF" 121.488,216.987 r90 top
R579 "0mR" "RES 0402/1005 RF" 123.52,216.987 r90 top
R580 "0mR" "RES 0402/1005 RF" 124.536,216.987 r90 top
R581 "0mR" "RES 0402/1005 RF" 122.504,214.955 r270 top
R582 "0mR" "RES 0402/1005 RF" 121.488,214.955 r270 top
R583 "0mR" "RES 0402/1005 RF" 123.52,214.955 r270 top
R584 "0mR" "RES 0402/1005 RF" 124.536,214.955 r270 top
R585 "0mR" "RES 0402/1005 RF" 120.872,196.601 r270 top
R586 "0mR" "RES 0402/1005 RF" 119.856,196.601 r270 top
R587 "0mR" "RES 0402/1005 RF" 121.888,196.601 r270 top
R588 "0mR" "RES 0402/1005 RF" 122.904,196.601 r270 top
R589 "0mR" "RES 0402/1005 RF" 120.872,198.633 r90 top
R590 "0mR" "RES 0402/1005 RF" 119.856,198.633 r90 top
R591 "0mR" "RES 0402/1005 RF" 121.888,198.633 r90 top
R592 "0mR" "RES 0402/1005 RF" 122.904,198.633 r90 top
R593 "0mR" "RES 0402/1005 RF" 346.545,249.003 r270 top
R594 "0mR" "RES 0402/1005 RF" 347.561,249.003 r270 top
R595 "0mR" "RES 0402/1005 RF" 345.529,251.035 r90 top
R596 "0mR" "RES 0402/1005 RF" 344.513,251.035 r90 top
R597 "0mR" "RES 0402/1005 RF" 346.545,251.035 r90 top
R598 "0mR" "RES 0402/1005 RF" 347.561,251.035 r90 top
R599 "1kR" "RES 0402/1005 RF" 363.753,50.691 r90 top
R600 "0mR" "RES 0402/1005 RF" 367.741,116.091 r90 top
R601 "0mR" "RES 0402/1005 RF" 360.87,115.067 r90 top
R602 "10kR" "RES 0402/1005 RF" 378.714,52.959 r0 top
R603 "10kR" "RES 0402/1005 RF" 374.383,52.959 r0 top
R604 "10kR" "RES 0402/1005 RF" 370.053,52.959 r0 top
R605 "10kR" "RES 0402/1005 RF" 365.722,52.959 r0 top
R606 "10kR" "RES 0402/1005 RF" 361.391,52.959 r0 top
R607 "0mR" "RES 0402/1005 RF" 361.391,58.179 r0 top
R608 "10kR" "RES 0402/1005 RF" 365.722,27.521 r0 top
R609 "10kR" "RES 0402/1005 RF" 361.074,26.67 r0 top
R610 "1.33kR" "RES 0402/1005 RF" 67.378,240.02 r90 top
R611 "1.33kR" "RES 0402/1005 RF" 67.113,230.597 r270 top
R612 "270R" "RES 0402/1005 RF" 59.342,241.891 r180 top
R613 "2.4R" "RES 1206/3216" 90.765,245.884 r270 top
R614 "270R" "RES 0402/1005 RF" 59.242,230.712 r180 top
R615 "10kR" "RES 0402/1005 RF" 60.606,234.739 r0 bottom
R616 "2.4R" "RES 1206/3216" 90.717,225.431 r90 top
R617 "PU5931FKMP70R004L" PU5931 137.735,295.465 r0 top
R618 "10kR" "RES 0402/1005 RF" 430.657,105.893 r0 top
R619 "1.91kR" "RES 0402/1005 RF" 69.532,182.474 r90 top
R620 "2kR" "RES 0402/1005 RF" 70.68,178.1 r180 top
R621 "147kR" "RES 0402/1005 RF" 65.137,183.819 r90 top
R622 "340kR" "RES 0402/1005 RF" 65.175,175.443 r270 top
R623 "1.43kR" "RES 0402/1005 RF" 63.12,175.457 r90 top
R624 "15kR" "RES 0402/1005 RF" 63.175,183.76 r270 top
R625 "1.4kR" "RES 0201/0603" 67.001,210.554 r270 top
R626 "200kR" "RES 0402/1005 RF" 59.997,210.161 r90 top
R627 "10.5kR" "RES 0402/1005 RF" 60.944,210.183 r270 top
R628 "750kR" "RES 0402/1005 RF" 69.132,200.233 r270 top
R629 "Resistance" "RES 0402/1005 RF" 68.656,206.964 r180 top
R630 "10kR" "RES 0402/1005 RF" 51.568,193.051 r180 top
R631 "5.9kR" "RES 0402/1005 RF" 61.938,202.273 r90 top
R632 "100kR" "RES 0402/1005 RF" 382.981,55.689 r0 top
R633 "100kR" "RES 0402/1005 RF" 387.312,55.689 r0 top
R634 "100kR" "RES 0402/1005 RF" 391.643,55.689 r0 top
R635 "10k" "RES 0402/1005 RF" 317.259,29.858 r90 top
R636 "0R" "RES 0402/1005 RF" 295.669,29.858 r90 top
R637 "0R" "RES 0402/1005 RF" 288.29,29.858 r90 top
R638 "0R" "RES 0402/1005 RF" 273.558,29.858 r90 top
R639 "0R" "RES 0402/1005 RF" 244.894,29.858 r90 top
R640 "0R" "RES 0402/1005 RF" 666.344,68.89 r90 top
R641 "0R" "RES 0402/1005 RF" 650.253,48.476 r90 top
R642 "0R" "RES 0402/1005 RF" 635.508,48.476 r90 top
R643 "0R" "RES 0402/1005 RF" 620.776,48.476 r90 top
R644 "9.1kR" "RES 0402/1005 RF" 370.04,50.47 r0 top
R645 "13kR" "RES 0402/1005 RF" 360.973,45.402 r0 top
R646 "100kR" "RES 0402/1005 RF" 361.391,50.47 r0 top
R647 "100kR" "RES 0402/1005 RF" 141.656,34.608 r0 top
R648 "2R" "RES 0402/1005 RF" 154.292,35.814 r0 top
R649 "10kR" "RES 0402/1005 RF" 162.547,30.607 r180 top
R650 "100MR" "RES 0402/1005 RF" 128.88,29.426 r0 top
R651 "10kR" "RES 0402/1005 RF" 125.993,18.085 r270 top
R652 "1MR" "RES 0402/1005 RF" 156.832,30.264 r90 top
R653 "20R" "RES 0402/1005 RF" 128.753,12.451 r270 top
R654 "100R" "RES 0402/1005 RF" 163.322,26.238 r180 top
R655 "10kR" "RES 0402/1005 RF" 156.756,26.429 r270 top
R656 "10kR" "RES 0402/1005 RF" 123.876,11.633 r270 top
R657 "100R" "RES 0402/1005 RF" 136.436,9.436 r270 top
R658 "10kR" "RES 0402/1005 RF" 130.238,8.776 r270 top
R659 "10kR" "RES 0402/1005 RF" 426.326,105.893 r0 top
R660 "10kR" "RES 0402/1005 RF" 421.996,105.893 r0 top
R661 "10kR" "RES 0402/1005 RF" 417.665,105.893 r0 top
R662 "10kR" "RES 0402/1005 RF" 413.334,105.893 r0 top
R663 "10kR" "RES 0402/1005 RF" 409.016,105.893 r0 top
R664 "10kR" "RES 0402/1005 RF" 404.685,105.893 r0 top
R665 "0mR" "RES 0402/1005 RF" 39.014,209.378 r270 top
R666 "12mR" "RES 1206/3216" 45.266,205.057 r90 top
R667 "24.9kR" "RES 0402/1005 RF" 42.528,202.265 r180 top
R668 "20kR" "RES 0402/1005 RF" 362.941,215.982 r90 top
R669 "0mR" "RES 0402/1005 RF" 38.887,200.381 r270 top
R670 "0mR" "RES 0402/1005 RF" 37.668,200.388 r270 top
R671 "1.87kR" "RES 0402/1005 RF" 218.007,323.545 r0 top
R672 "1.5kR" "RES 0402/1005 RF" 254.433,334.124 r0 top
R673 "1.87kR" "RES 0402/1005 RF" 241.467,334.124 r0 top
R674 "15kR" "RES 0402/1005 RF" 232.818,334.124 r0 top
R675 "0mR" "RES 0402/1005 RF" 366.883,133.883 r0 top
R676 "20kR" "RES 0402/1005 RF" 233.582,321.424 r0 top
R677 "95.3kR" "RES 0402/1005 RF" 44.716,192.483 r270 top
R678 "95.3kR" "RES 0402/1005 RF" 43.658,192.483 r270 top
R679 "95.3kR" "RES 0402/1005 RF" 45.775,195.483 r90 top
R680 "95.3kR" "RES 0402/1005 RF" 43.658,195.483 r90 top
R681 "24.9kR" "RES 0402/1005 RF" 51.568,194.019 r180 top
R682 "7.5kR" "RES 0402/1005 RF" 45.775,192.483 r90 top
R683 "4.87kR" "RES 0402/1005 RF" 42.6,192.483 r90 top
R684 "7.15kR" "RES 0402/1005 RF" 44.716,195.483 r270 top
R685 "5.9kR" "RES 0402/1005 RF" 42.6,195.483 r270 top
R686 "412kR" "RES 0402/1005 RF" 56.27,215.062 r90 top
R687 "57.6kR" "RES 0402/1005 RF" 61.953,210.719 r270 top
R688 "10kR" "RES 0402/1005 RF" 400.355,105.893 r0 top
R689 "20kR" "RES 0402/1005 RF" 160.795,347.612 r90 top
R690 "100kR" "RES 0402/1005 RF" 159.652,347.612 r90 top
R691 "20kR" "RES 0402/1005 RF" 158.102,351.698 r0 top
R692 "0R" "RES 0402/1005 RF" 360.883,130.988 r90 top
R693 "0mR" "RES 0402/1005 RF" 399.136,142.354 r90 top
R694 "1kR" "RES 0402/1005 RF" 231.723,323.635 r90 top
R695 "100R" "RES 0402/1005 RF" 165.024,277.812 r90 top
R696 "0mR" "RES 0402/1005 RF" 377.025,142.354 r90 top
R697 "0mR" "RES 0402/1005 RF" 441.414,62.446 r90 top
R697_1 "0mR" "RES 0402/1005 RF" 61.554,108.973 r180 top (schematic designator R697)
R698 "0mR" "RES 0402/1005 RF" 434.048,62.446 r90 top
R698_1 "0mR" "RES 0402/1005 RF" 64.305,108.973 r0 top (schematic designator R698)
R699 "0mR" "RES 0402/1005 RF" 426.682,62.446 r90 top
R699_1 "0mR" "RES 0402/1005 RF" 61.554,109.979 r180 top (schematic designator R699)
R700 "0mR" "RES 0402/1005 RF" 419.316,62.446 r90 top
R700_1 "0mR" "RES 0402/1005 RF" 64.305,109.979 r0 top (schematic designator R700)
R701 "0mR" "RES 0402/1005 RF" 412.458,62.446 r90 top
R701_1 "0mR" "RES 0402/1005 RF" 61.554,111.006 r180 top (schematic designator R701)
R702 "0mR" "RES 0402/1005 RF" 405.092,62.446 r90 top
R702_1 "0mR" "RES 0402/1005 RF" 64.305,111.006 r0 top (schematic designator R702)
R703 "0mR" "RES 0402/1005 RF" 397.713,62.446 r90 top
R703_1 "0mR" "RES 0402/1005 RF" 77.381,130.791 r180 top (schematic designator R703)
R704 "0mR" "RES 0402/1005 RF" 390.347,62.446 r90 top
R704_1 "0mR" "RES 0402/1005 RF" 80.094,130.791 r0 top (schematic designator R704)
R705 "0mR" "RES 0402/1005 RF" 382.981,62.446 r90 top
R705_1 "0mR" "RES 0402/1005 RF" 77.381,131.756 r180 top (schematic designator R705)
R706 "0mR" "RES 0402/1005 RF" 375.615,62.446 r90 top
R706_1 "0mR" "RES 0402/1005 RF" 80.094,131.756 r0 top (schematic designator R706)
R707 "0mR" "RES 0402/1005 RF" 368.249,62.446 r90 top
R707_1 "0mR" "RES 0402/1005 RF" 77.381,132.741 r180 top (schematic designator R707)
R708 "0mR" "RES 0402/1005 RF" 360.883,62.446 r90 top
R708_1 "0mR" "RES 0402/1005 RF" 80.094,132.741 r0 top (schematic designator R708)
R709 "2.2kR" "RES 0402/1005 RF" 110.217,285.162 r270 bottom
R710 "10kR" "RES 0402/1005 RF" 643.674,109.855 r90 top
R711 "0mR" "RES 0402/1005 RF" 629.958,109.855 r90 top
R712 "0mR" "RES 0402/1005 RF" 636.562,109.855 r90 top
R713 "0mR" "RES 0402/1005 RF" 622.846,109.855 r90 top
R714 "2.2kR" "RES 0402/1005 RF" 513.08,109.855 r90 top
R715 "10kR" "RES 0402/1005 RF" 360.807,108.489 r90 top
R716 "261R" "RES 0402/1005 RF" 389.585,93.218 r90 top
R717 "261R" "RES 0402/1005 RF" 382.473,93.218 r90 top
R718 "261R" "RES 0402/1005 RF" 375.361,93.218 r90 top
R719 "261R" "RES 0402/1005 RF" 368.249,93.218 r90 top
R720 "261R" "RES 0402/1005 RF" 360.883,93.218 r90 top
R721 "10k" "RES 0402/1005 RF" 310.401,29.858 r90 top
R722 "0R" "RES 0402/1005 RF" 280.924,29.858 r90 top
R723 "0R" "RES 0402/1005 RF" 252.26,29.858 r90 top
R724 "0R" "RES 0402/1005 RF" 237.528,29.858 r90 top
R725 "0R" "RES 0402/1005 RF" 667.969,61.589 r90 top
R726 "0R" "RES 0402/1005 RF" 642.874,48.476 r90 top
R727 "0R" "RES 0402/1005 RF" 628.142,48.476 r90 top
R728 "0R" "RES 0402/1005 RF" 613.41,48.476 r90 top
R729 "0R" "RES 0402/1005 RF" 606.044,48.476 r90 top
R730 "4.7kR" "RES 0402/1005 RF" 269.418,92.545 r90 top
R731 "4.7kR" "RES 0402/1005 RF" 276.784,92.545 r90 top
R732 "4.7kR" "RES 0402/1005 RF" 283.642,92.545 r90 top
R733 "4.7kR" "RES 0402/1005 RF" 291.008,92.545 r90 top
R734 "4.7kR" "RES 0402/1005 RF" 298.387,92.545 r90 top
R735 "10kR" "RES 0402/1005 RF" 382.981,193.865 r90 top
R736 "0mR" "RES 0402/1005 RF" 360.883,118.783 r90 top
R737 "10kR" "RES 0402/1005 RF" 370.802,65.601 r90 top
R738 "0mR" "RES 0402/1005 RF" 395.821,72.446 r90 top
R738_1 "0mR" "RES 0402/1005 RF" 78.943,108.682 r180 top (schematic designator R738)
R739 "0mR" "RES 0402/1005 RF" 390.747,72.281 r90 top
R739_1 "0mR" "RES 0402/1005 RF" 81.658,108.682 r0 top (schematic designator R739)
R740 "0mR" "RES 0402/1005 RF" 381.305,72.014 r90 top
R740_1 "0mR" "RES 0402/1005 RF" 78.942,109.79 r180 top (schematic designator R740)
R741 "0mR" "RES 0402/1005 RF" 375.615,72.314 r90 top
R741_1 "0mR" "RES 0402/1005 RF" 81.658,109.79 r0 top (schematic designator R741)
R742 "0mR" "RES 0402/1005 RF" 368.249,72.314 r90 top
R742_1 "0mR" "RES 0402/1005 RF" 78.942,110.815 r180 top (schematic designator R742)
R743 "0mR" "RES 0402/1005 RF" 360.883,72.314 r90 top
R743_1 "0mR" "RES 0402/1005 RF" 81.658,110.815 r0 top (schematic designator R743)
R744 "10kR" "RES 0402/1005 RF" 396.024,105.893 r0 top
R745 "20kR" "RES 0402/1005 RF" 206.874,311.64 r270 top
R746 "10kR" "RES 0402/1005 RF" 404.584,168.974 r90 top
R747 "10kR" "RES 0402/1005 RF" 411.95,168.974 r90 top
R748 "10kR" "RES 0402/1005 RF" 419.316,168.974 r90 top
R749 "10kR" "RES 0402/1005 RF" 426.682,168.974 r90 top
R750 "10kR" "RES 0402/1005 RF" 434.048,168.974 r90 top
R751 "10kR" "RES 0402/1005 RF" 441.414,168.974 r90 top
R752 "10kR" "RES 0402/1005 RF" 448.272,168.974 r90 top
R753 "10kR" "RES 0402/1005 RF" 455.651,168.974 r90 top
R754 "10kR" "RES 0402/1005 RF" 463.017,168.974 r90 top
R755 "10kR" "RES 0402/1005 RF" 470.383,168.974 r90 top
R756 "10kR" "RES 0402/1005 RF" 477.749,168.974 r90 top
R757 "10kR" "RES 0402/1005 RF" 485.115,168.974 r90 top
R758 "0mR" "RES 0402/1005 RF" 397.205,168.974 r90 top
R758_1 "0mR" "RES 0402/1005 RF" 62.638,76.815 r180 top (schematic designator R758)
R759 "0mR" "RES 0402/1005 RF" 389.839,168.974 r90 top
R759_1 "0mR" "RES 0402/1005 RF" 65.529,76.806 r0 top (schematic designator R759)
R760 "0mR" "RES 0402/1005 RF" 382.473,168.974 r90 top
R760_1 "0mR" "RES 0402/1005 RF" 62.64,77.822 r180 top (schematic designator R760)
R761 "0mR" "RES 0402/1005 RF" 375.615,168.974 r90 top
R761_1 "0mR" "RES 0402/1005 RF" 65.529,77.813 r0 top (schematic designator R761)
R762 "0mR" "RES 0402/1005 RF" 368.249,168.974 r90 top
R762_1 "0mR" "RES 0402/1005 RF" 62.64,78.813 r180 top (schematic designator R762)
R763 "0mR" "RES 0402/1005 RF" 360.883,168.974 r90 top
R763_1 "0mR" "RES 0402/1005 RF" 65.529,78.803 r0 top (schematic designator R763)
R764 "WSHP28184L000FEA" WSHP2818 391.008,83.947 r90 top
R765 "0mR" "RES 0402/1005 RF" 375.615,193.865 r90 top
R766 "0mR" "RES 0402/1005 RF" 368.249,193.865 r90 top
R767 "0mR" "RES 0402/1005 RF" 360.883,193.865 r90 top
R768 "0mR" "RES 0402/1005 RF" 776.059,202.59 r90 top
R769 "0mR" "RES 0402/1005 RF" 768.68,202.59 r90 top
R770 "0mR" "RES 0402/1005 RF" 761.314,202.59 r90 top
R771 "0mR" "RES 0402/1005 RF" 754.456,202.59 r90 top
R772 "0mR" "RES 0402/1005 RF" 95.331,345.084 r90 top
R773 "0mR" "RES 0402/1005 RF" 94.055,345.231 r90 top
R774 "0mR" "RES 0402/1005 RF" 172.834,355.491 r90 top
R775 "0mR" "RES 0402/1005 RF" 171.751,355.694 r90 top
R776 "0mR" "RES 0402/1005 RF" 152.468,308.038 r180 top
R777 "0mR" "RES 0402/1005 RF" 152.468,306.984 r180 top
R778 "0mR" "RES 0402/1005 RF" 152.475,305.638 r180 top
R779 "0mR" "RES 0402/1005 RF" 152.425,304.013 r180 top
R780 "0mR" "RES 0402/1005 RF" 688.149,202.59 r90 top
R781 "0mR" "RES 0402/1005 RF" 681.291,202.59 r90 top
R782 "0mR" "RES 0402/1005 RF" 673.925,202.59 r90 top
R783 "0mR" "RES 0402/1005 RF" 666.559,202.59 r90 top
R784 "0mR" "RES 0402/1005 RF" 651.827,202.59 r90 top
R785 "0mR" "RES 0402/1005 RF" 644.449,202.59 r90 top
R786 "0mR" "RES 0402/1005 RF" 637.083,202.59 r90 top
R787 "0mR" "RES 0402/1005 RF" 629.717,202.59 r90 top
R788 "0mR" "RES 0402/1005 RF" 622.351,202.59 r90 top
R789 "0mR" "RES 0402/1005 RF" 614.985,202.59 r90 top
R790 "0mR" "RES 0402/1005 RF" 104.927,440.855 r90 top
R791 "0mR" "RES 0402/1005 RF" 102.375,440.645 r90 top
R792 "0mR" "RES 0402/1005 RF" 100.063,440.721 r90 top
R793 "0mR" "RES 0402/1005 RF" 97.46,440.492 r90 top
R794 "0mR" "RES 0402/1005 RF" 95.136,440.746 r90 top
R795 "0mR" "RES 0402/1005 RF" 92.494,440.81 r90 top
R796 "0mR" "RES 0402/1005 RF" 556.552,202.59 r90 top
R797 "0mR" "RES 0402/1005 RF" 541.82,202.59 r90 top
R798 "0mR" "RES 0402/1005 RF" 527.088,202.59 r90 top
R799 "0mR" "RES 0402/1005 RF" 519.722,202.59 r90 top
R800 "0mR" "RES 0402/1005 RF" 63.119,343.835 r90 top
R801 "0mR" "RES 0402/1005 RF" 56.261,343.835 r90 top
R802 "0mR" "RES 0402/1005 RF" 48.895,343.835 r90 top
R803 "0mR" "RES 0402/1005 RF" 490.753,202.59 r90 top
R804 "0mR" "RES 0402/1005 RF" 483.387,202.59 r90 top
R805 "0mR" "RES 0402/1005 RF" 468.655,202.59 r90 top
R806 "0mR" "RES 0402/1005 RF" 461.289,202.59 r90 top
R807 "0mR" "RES 0402/1005 RF" 453.923,202.59 r90 top
R808 "0mR" "RES 0402/1005 RF" 431.825,202.59 r90 top
R809 "0mR" "RES 0402/1005 RF" 417.538,202.59 r90 top
R810 "0mR" "RES 0402/1005 RF" 410.413,202.59 r90 top
R811 "0mR" "RES 0402/1005 RF" 396.443,202.59 r90 top
R812 "0mR" "RES 0402/1005 RF" 389.331,202.59 r90 top
R813 "0mR" "RES 0402/1005 RF" 382.219,202.59 r90 top
R814 "0mR" "RES 0402/1005 RF" 375.107,202.59 r90 top
R815 "0mR" "RES 0402/1005 RF" 367.995,202.59 r90 top
R816 "0mR" "RES 0402/1005 RF" 360.883,202.59 r90 top
R817 "10kR" "RES 0402/1005 RF" 391.693,105.893 r0 top
R818 "10kR" "RES 0402/1005 RF" 387.363,105.893 r0 top
R819 "10kR" "RES 0402/1005 RF" 383.045,105.893 r0 top
R820 "10kR" "RES 0402/1005 RF" 378.714,105.893 r0 top
R821 "10kR" "RES 0402/1005 RF" 374.383,105.893 r0 top
R822 "10kR" "RES 0402/1005 RF" 370.053,105.893 r0 top
R823 "10kR" "RES 0402/1005 RF" 365.722,105.893 r0 top
R824 "10kR" "RES 0402/1005 RF" 361.391,105.893 r0 top
R832 "100kR" "RES 0402/1005 RF" 426.682,28.029 r90 top
R833 "10kR" "RES 0402/1005 RF" 419.316,28.029 r90 top
R834 "10kR" "RES 0402/1005 RF" 411.95,28.029 r90 top
R835 "100kR" "RES 0402/1005 RF" 34.397,201.93 r0 top
R836 "10kR" "RES 0402/1005 RF" 416.484,5.855 r90 top
R837 "10kR" "RES 0402/1005 RF" 388.76,23.99 r90 top
R838 "20kR" "RES 0402/1005 RF" 382.473,28.029 r90 top
R839 "10kR" "RES 0402/1005 RF" 375.107,28.029 r90 top
R840 "20kR" "RES 0402/1005 RF" 367.741,28.029 r90 top
R841 "20kR" "RES 0402/1005 RF" 360.883,28.029 r90 top
S1 "Mode Switch" SO8_N 230.073,348.386 r180 top
S2 "430181038816" 430181038816 402.45,61.481 r90 top
S3 "430181038816" 430181038816 393.903,62.357 r90 top
S4 "430181038816" 430181038816 441.554,41.999 r90 top
S5 "Mode Switch" SO8_N 382.27,20.13 r0 top
S6 "430181038816" 430181038816 432.473,94.424 r90 top
S7 "430181038816" 430181038816 569.138,135.871 r90 top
